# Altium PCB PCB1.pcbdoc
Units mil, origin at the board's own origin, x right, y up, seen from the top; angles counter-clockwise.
Board outline 3289.42 x 4778.44 mil, 2 copper layers (Top Layer, Bottom Layer); 55 components, 54 nets, 200 pads, 63 vias.
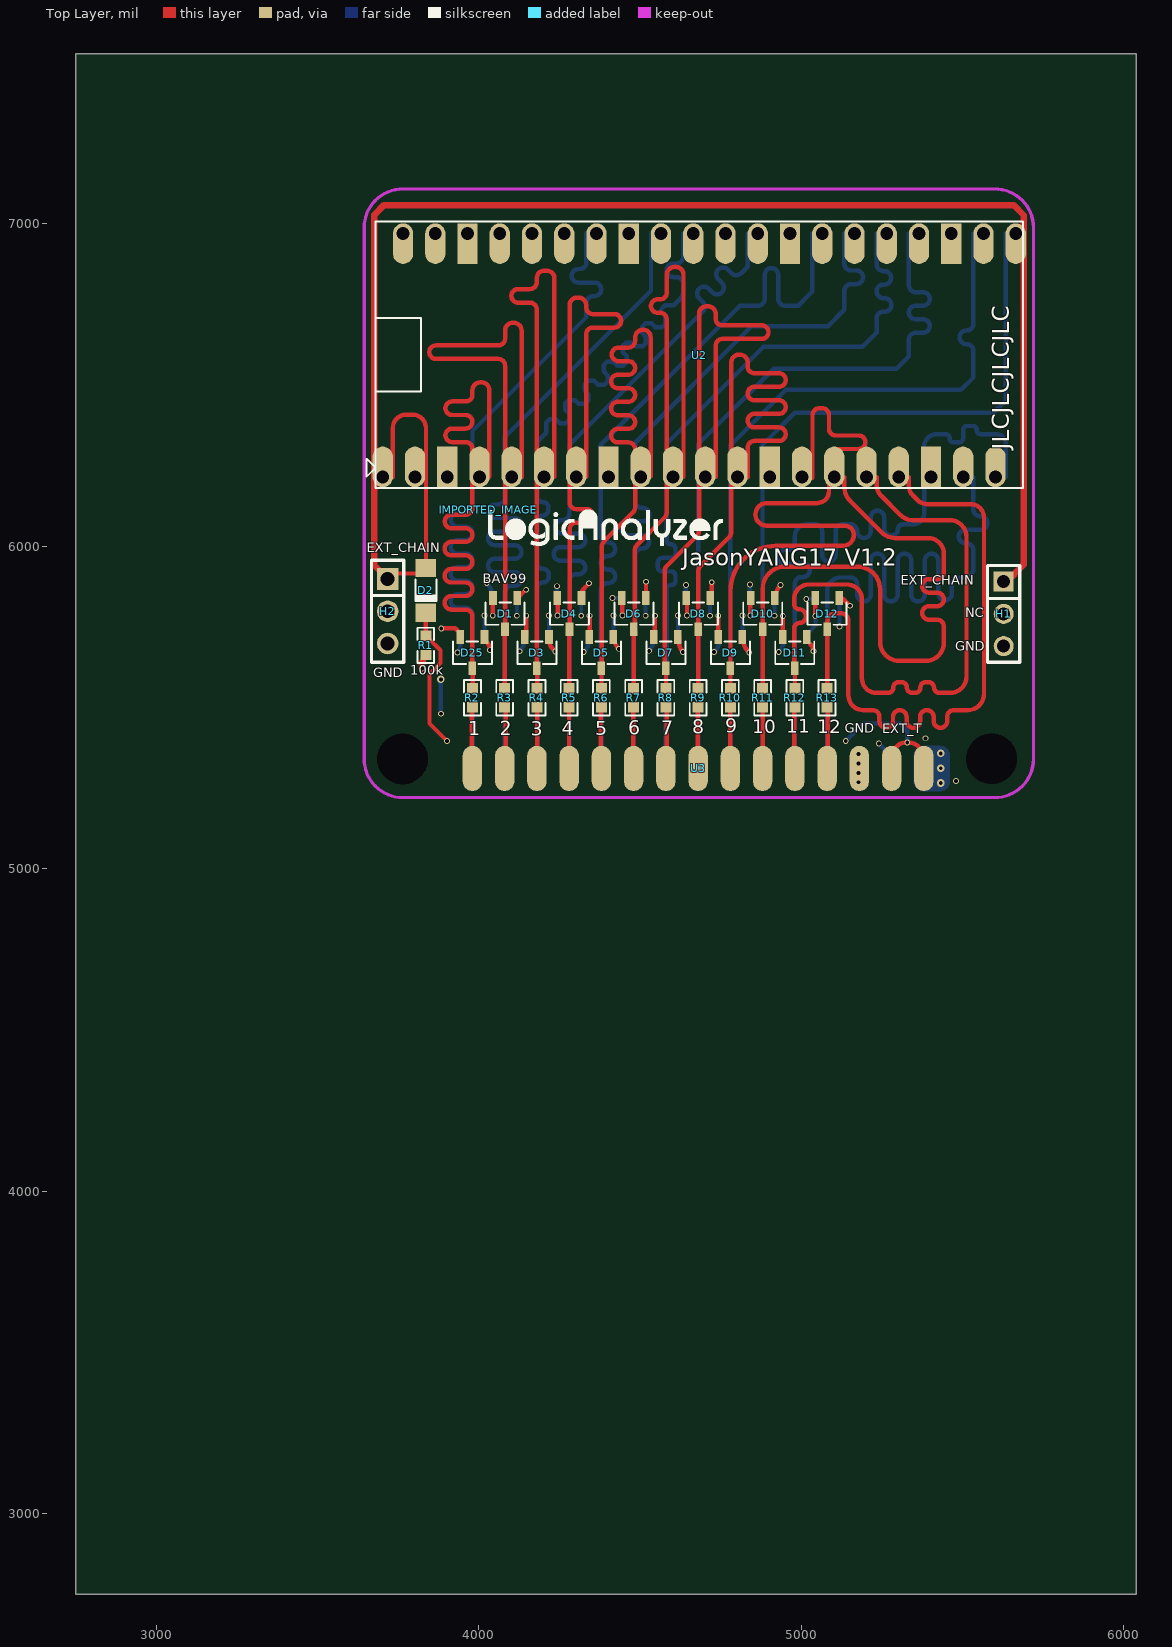
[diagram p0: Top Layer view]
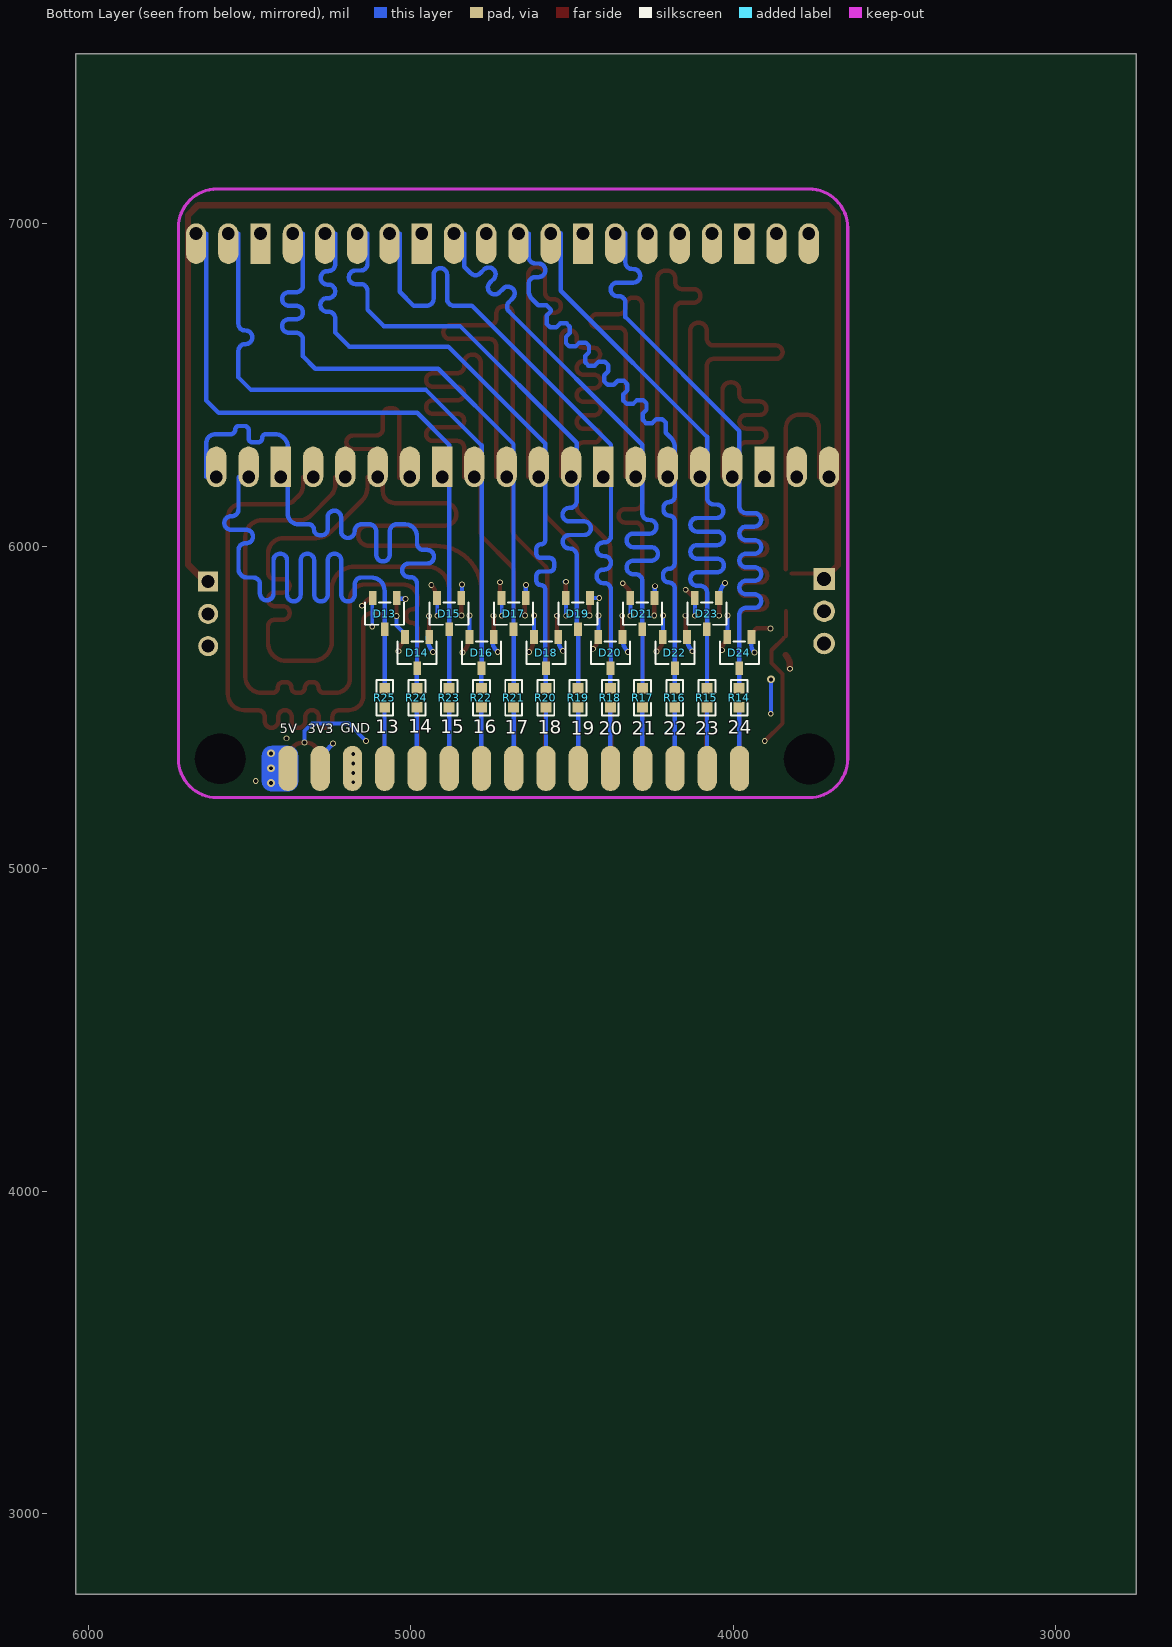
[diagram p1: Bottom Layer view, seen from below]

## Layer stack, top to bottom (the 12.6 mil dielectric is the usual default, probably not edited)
Top Layer: signal copper (thickness not stored)
Dielectric: dielectric 12.6, FR-4, Dk 4.8
Bottom Layer: signal copper (thickness not stored)

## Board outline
6039.42,2750 2750,2750 2750,7528.44 6039.42,7528.44
cut-out: 3842.69,5340.86 ccw(c3764.19,5340.86) 3685.69,5340.86 ccw(c3764.19,5340.86)
cut-out: 5669.28,5341.59 ccw(c5590.78,5341.59) 5512.28,5341.59 ccw(c5590.78,5341.59)

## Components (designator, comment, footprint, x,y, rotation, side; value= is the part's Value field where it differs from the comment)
D1 "BAV99,215" SOT-23-3_L2.9-W1.6-P1.90-LS2.8-BR 4081.8,5791.53 r90 top
D2 "FDLL4148" SOD-80_L3.5-W1.5-RD 3836.2,5863.79 r90 top
D3 "BAV99,215" SOT-23-3_L2.9-W1.6-P1.90-LS2.8-BR 4180.63,5670.41 r90 top
D4 "BAV99,215" SOT-23-3_L2.9-W1.6-P1.90-LS2.8-BR 4281.59,5791.53 r90 top
D5 "BAV99,215" SOT-23-3_L2.9-W1.6-P1.90-LS2.8-BR 4380.57,5670.41 r90 top
D6 "BAV99,215" SOT-23-3_L2.9-W1.6-P1.90-LS2.8-BR 4481.39,5791.53 r90 top
D7 "BAV99,215" SOT-23-3_L2.9-W1.6-P1.90-LS2.8-BR 4580.5,5670.41 r90 top
D8 "BAV99,215" SOT-23-3_L2.9-W1.6-P1.90-LS2.8-BR 4681.19,5791.53 r90 top
D9 "BAV99,215" SOT-23-3_L2.9-W1.6-P1.90-LS2.8-BR 4780.44,5670.41 r90 top
D10 "BAV99,215" SOT-23-3_L2.9-W1.6-P1.90-LS2.8-BR 4880.98,5791.53 r90 top
D11 "BAV99,215" SOT-23-3_L2.9-W1.6-P1.90-LS2.8-BR 4980.37,5670.41 r90 top
D12 "BAV99,215" SOT-23-3_L2.9-W1.6-P1.90-LS2.8-BR 5080.78,5791.53 r90 top
D13 "BAV99,215" SOT-23-3_L2.9-W1.6-P1.90-LS2.8-BR 5080.78,5791.53 r90 bottom
D14 "BAV99,215" SOT-23-3_L2.9-W1.6-P1.90-LS2.8-BR 4980.37,5670.41 r90 bottom
D15 "BAV99,215" SOT-23-3_L2.9-W1.6-P1.90-LS2.8-BR 4880.98,5791.53 r90 bottom
D16 "BAV99,215" SOT-23-3_L2.9-W1.6-P1.90-LS2.8-BR 4780.44,5670.41 r90 bottom
D17 "BAV99,215" SOT-23-3_L2.9-W1.6-P1.90-LS2.8-BR 4681.19,5791.53 r90 bottom
D18 "BAV99,215" SOT-23-3_L2.9-W1.6-P1.90-LS2.8-BR 4580.5,5670.41 r90 bottom
D19 "BAV99,215" SOT-23-3_L2.9-W1.6-P1.90-LS2.8-BR 4481.39,5791.53 r90 bottom
D20 "BAV99,215" SOT-23-3_L2.9-W1.6-P1.90-LS2.8-BR 4380.57,5670.41 r90 bottom
D21 "BAV99,215" SOT-23-3_L2.9-W1.6-P1.90-LS2.8-BR 4281.59,5791.53 r90 bottom
D22 "BAV99,215" SOT-23-3_L2.9-W1.6-P1.90-LS2.8-BR 4180.63,5670.41 r90 bottom
D23 "BAV99,215" SOT-23-3_L2.9-W1.6-P1.90-LS2.8-BR 4081.8,5791.53 r90 bottom
D24 "BAV99,215" SOT-23-3_L2.9-W1.6-P1.90-LS2.8-BR 3980.7,5670.41 r90 bottom
D25 "BAV99,215" SOT-23-3_L2.9-W1.6-P1.90-LS2.8-BR 3980.7,5670.41 r90 top
H1 "HDR-F_2.54_1x3P" HDR-TH_3P-P2.54-V-F 5628.17,5790.73 r270 top
H2 "HDR-M_2.54_1x3P" HDR-TH_3P-P2.54-V-M 3717.94,5799 r270 top
IMPORTED_IMAGE "IMPORTED_IMAGE" IMPORTED_IMAGE 4030.01,6114.17 r0 top
R1 "0603WAF1003T5E" R0603 3836.2,5693.26 r90 top
R2 "RC0603FR-07220RL" R0603 3980.7,5530.62 r270 top
R3 "RC0603FR-07220RL" R0603 4080.69,5530.62 r270 top
R4 "RC0603FR-07220RL" R0603 4180.68,5530.62 r270 top
R5 "RC0603FR-07220RL" R0603 4280.67,5530.62 r270 top
R6 "RC0603FR-07220RL" R0603 4380.66,5530.62 r270 top
R7 "RC0603FR-07220RL" R0603 4480.65,5530.62 r270 top
R8 "RC0603FR-07220RL" R0603 4580.64,5530.62 r270 top
R9 "RC0603FR-07220RL" R0603 4680.62,5530.62 r270 top
R10 "RC0603FR-07220RL" R0603 4780.61,5530.62 r270 top
R11 "RC0603FR-07220RL" R0603 4880.6,5530.62 r270 top
R12 "RC0603FR-07220RL" R0603 4980.59,5530.62 r270 top
R13 "RC0603FR-07220RL" R0603 5080.58,5530.62 r270 top
R14 "RC0603FR-07220RL" R0603 3981.38,5530.62 r90 bottom
R15 "RC0603FR-07220RL" R0603 4081.31,5530.62 r90 bottom
R16 "RC0603FR-07220RL" R0603 4181.24,5530.62 r90 bottom
R17 "RC0603FR-07220RL" R0603 4281.17,5530.62 r90 bottom
R18 "RC0603FR-07220RL" R0603 4381.09,5530.62 r90 bottom
R19 "RC0603FR-07220RL" R0603 4481.02,5530.62 r90 bottom
R20 "RC0603FR-07220RL" R0603 4580.95,5530.62 r90 bottom
R21 "RC0603FR-07220RL" R0603 4680.88,5530.62 r90 bottom
R22 "RC0603FR-07220RL" R0603 4780.8,5530.62 r90 bottom
R23 "RC0603FR-07220RL" R0603 4880.73,5530.62 r90 bottom
R24 "RC0603FR-07220RL" R0603 4980.66,5530.62 r90 bottom
R25 "RC0603FR-07220RL" R0603 5080.58,5530.62 r90 bottom
U2 "树莓派pico" 树莓派pico多层 5684.16,6181.42 r90 top
U3 "双排针母座2.54 2*15P" HDR-TH_30P-P2.54-V-F-R2-C15-S2.54-A 4628.47,5298.24 r90 top

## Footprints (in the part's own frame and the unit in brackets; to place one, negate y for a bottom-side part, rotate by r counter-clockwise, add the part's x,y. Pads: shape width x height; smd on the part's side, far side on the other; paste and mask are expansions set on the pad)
HDR-TH_3P-P2.54-V-F [mil]
  rect 62x62 hole 40.16 mask+2: 1(-100,0)
  round 62 hole 40.16 mask+2: 2(0,0) 3(100,0)
  silkscreen extent -150,-50 150,50
HDR-TH_3P-P2.54-V-M [mm]
  rect 1.7x1.7 hole 1.1 mask+0.051: 1(-2.54,0)
  round 1.7 hole 1.1 mask+0.051: 2(0,0) 3(2.54,0)
  silkscreen extent -4.02,-1.27 4.02,1.27
HDR-TH_30P-P2.54-V-F-R2-C15-S2.54-A [mil]
  oval 140x60 smd mask+2: 1(13.26,647.77) 2(13.26,547.77) 3(13.26,447.77) 4(13.26,347.77) 5(13.26,247.77) 6(13.26,147.77) 7(13.26,47.77) 8(13.26,-52.23) 9(13.26,-152.23) 10(13.26,-252.23) 11(13.26,-352.23) 12(13.26,-452.23) 13(13.26,-552.23) 14(13.26,-652.23) 15(13.26,-752.23)
  oval 140x60 smd far side mask+2: 16(13.26,-752.23) 17(13.26,-652.23) 18(13.26,-552.23) 19(13.26,-452.23) 20(13.26,-352.23) 21(13.26,-252.23) 22(13.26,-152.23) 23(13.26,-52.23) 24(13.26,47.77) 25(13.26,147.77) 26(13.26,247.77) 27(13.26,347.77) 28(13.26,447.77) 29(13.26,547.77) 30(13.26,647.77)
IMPORTED_IMAGE [mil]
  silkscreen extent 0,-112 727,0
R0603 [mil]
  rect 31.75x34.02 smd paste-3937.01 mask+2: 1(-29.66,0) 2(29.66,0)
  silkscreen extent -55,-26 55,26
SOD-80_L3.5-W1.5-RD [mm]
  rect 1.44x1.62 smd mask+0.051: 1(-1.765,0) 2(1.765,0)
  silkscreen extent -0.84,-0.83 0.84,0.83
SOT-23-3_L2.9-W1.6-P1.90-LS2.8-BR [mm]
  rect 1.07x0.6 smd mask+0.051: 1(1.235,-0.95) 2(1.235,0.95) 3(-1.235,0)
  silkscreen extent -0.88,-1.54 0.88,1.54
树莓派pico多层 [mm]
  oval 3.2x1.6 hole 1 copper offset 0.8,0 paste+0 mask+0.102: 1(0.86,50.33) 2(0.86,47.79) 4(0.86,42.71) 5(0.86,40.17) 6(0.86,37.63) 7(0.86,35.09) 9(0.86,30.01) 10(0.86,27.47) 11(0.86,24.93) 12(0.86,22.39) 14(0.86,17.31) 15(0.86,14.77) 16(0.86,12.23) 17(0.86,9.69) 19(0.86,4.61) 20(0.86,2.07)
  rect 3.2x1.6 hole 1 copper offset 0.8,0 paste+0 mask+0.102: 3(0.86,45.25) 8(0.86,32.55) 13(0.86,19.85) 18(0.86,7.15)
  oval 3.2x1.6 hole 1 copper offset -0.8,0 paste+0 mask+0.102: 21(20.04,0.47) 22(20.04,3.01) 24(20.04,8.09) 25(20.04,10.63) 26(20.04,13.17) 27(20.04,15.71) 29(20.04,20.79) 30(20.04,23.33) 31(20.04,25.87) 32(20.04,28.41) 34(20.04,33.49) 35(20.04,36.03) 36(20.04,38.57) 37(20.04,41.11) 39(20.04,46.19) 40(20.04,48.73)
  rect 3.2x1.6 hole 1 copper offset -0.8,0 paste+0 mask+0.102: 23(20.04,5.55) 28(20.04,18.25) 33(20.04,30.95) 38(20.04,43.65)
  silkscreen extent 0,-0.1 21,51.6

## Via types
v1: diameter 18, hole 12, Top Layer to Bottom Layer, 54 vias
v2: diameter 18, hole 12.01, Top Layer to Bottom Layer, 5 vias
v3: diameter 24.02, hole 12.01, Top Layer to Bottom Layer, 3 vias
v4: diameter 24, hole 12, Top Layer to Bottom Layer, 1 vias

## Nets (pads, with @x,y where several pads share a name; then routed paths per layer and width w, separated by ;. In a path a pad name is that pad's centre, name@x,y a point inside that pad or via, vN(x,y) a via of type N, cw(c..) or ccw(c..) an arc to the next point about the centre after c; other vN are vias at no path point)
$1N6412: R2.2 U3.1 | length 188.7
  Top Layer w13.75: U3.1@3979.1,5310.98 R2.2@3979.1,5499.7
$1N6457: R3.2 U3.2 | length 179.5
  Top Layer w13.75: U3.2@4083.95,5316.22 R3.2@4083.95,5495.77
$1N6576: R4.2 U3.3 | length 157.4
  Top Layer w13.75: U3.3@4183.33,5346 4181.65,5347.68 4181.65,5500.27 R4.2@4183.33,5501.96
$1N6580: R5.2 U3.4 | length 180.9
  Top Layer w13.75: U3.4@4280.31,5315.86 R5.2@4280.31,5496.72
$1N6666: R6.2 U3.5 | length 159.9
  Top Layer w13.75: U3.5@4378.6,5337.48 R6.2@4378.6,5497.37
$1N6670: R7.2 U3.6 | length 179.7
  Top Layer w13.75: U3.6@4480.11,5318.1 R7.2@4480.11,5497.79
$1N6756: R8.2 U3.7 | length 168.4
  Top Layer w13.75: U3.7@4582.84,5329.02 R8.2@4582.84,5497.43
$1N6760: R9.2 U3.8 | length 151.4
  Top Layer w13.75: U3.8@4679.17,5345.4 R9.2@4679.17,5496.77
$1N6846: R10.2 U3.9 | length 159.2
  Top Layer w13.75: U3.9@4776.15,5342.12 4780.74,5346.71 R10.2@4780.74,5499.39
$1N6850: R11.2 U3.10 | length 180.4
  Top Layer w13.75: R11.2@4880.56,5500.48 4880.56,5325.38 U3.10@4884.27,5321.66
$1N6936: R12.2 U3.11 | length 170.1
  Top Layer w13.75: U3.11@4978.7,5327.2 R12.2@4978.7,5497.28
$1N6940: R13.2 U3.12 | length 161.9
  Top Layer w13.75: U3.12@5082.16,5335.53 R13.2@5082.16,5497.46
$1N7395: R25.1 U3.19 | length 189.5
  Bottom Layer w13.75: U3.19@5081.32,5311.99 R25.1@5081.32,5501.48
$1N7399: R24.1 U3.20 | length 190.8
  Bottom Layer w13.75: U3.20@4980.99,5312.32 R24.1@4980.99,5503.13
$1N7403: R23.1 U3.21 | length 189
  Bottom Layer w13.75: U3.21@4880.4,5309.73 R23.1@4880.4,5498.73
$1N7407: R22.1 U3.22 | length 185
  Bottom Layer w13.75: U3.22@4780.72,5309.73 R22.1@4780.72,5494.78
$1N7411: R21.1 U3.23 | length 186.5
  Bottom Layer w13.75: U3.23@4680.67,5310.6 R21.1@4680.67,5497.12
$1N7415: R20.1 U3.24 | length 188.5
  Bottom Layer w13.75: U3.24@4580.5,5311.58 R20.1@4580.5,5500.08
$1N7419: R19.1 U3.25 | length 191
  Bottom Layer w13.75: U3.25@4480.33,5311.09 R19.1@4480.33,5502.06
$1N7423: R18.1 U3.26 | length 189
  Bottom Layer w13.75: U3.26@4381.25,5310.88 R18.1@4381.25,5499.88
$1N7427: R17.1 U3.27 | length 185
  Bottom Layer w13.75: U3.27@4281.57,5310.88 R17.1@4281.57,5495.93
$1N7431: R16.1 U3.28 | length 186.5
  Bottom Layer w13.75: U3.28@4181.52,5311.75 R16.1@4181.52,5498.27
$1N7435: R15.1 U3.29 | length 188.5
  Bottom Layer w13.75: U3.29@4081.35,5312.73 R15.1@4081.35,5501.24
$1N7439: R14.1 U3.30 | length 191
  Bottom Layer w13.75: U3.30@3981.18,5312.24 R14.1@3981.18,5503.21
+3.3V: D1.2 D3.2 D4.2 D5.2 D6.2 D7.2 D8.2 D9.2 D10.2 D11.2 D12.2 D13.2 D14.2 D15.2 D16.2 D17.2 D18.2 D19.2 D20.2 D21.2 D22.2 D23.2 D24.2 D25.2 U2.36 U3.17 | length 6001
  Top Layer w13.75: v1(3883.9,5745.91) 3927.47,5745.91 3941.99,5731.39 D25.2@3941.99,5717.47 ; v1(4043.93,5785.29) D1.2@4043.93,5841.22 ; D3.2@4142.89,5717.97 4147.53,5722.61 v1(4147.53,5785.32) ; v1(4244.76,5785.5) D4.2@4244.76,5841.38 ; D5.2@4344.12,5721.22 v1(4344.12,5785.29) ; v1(4445.85,5785.55) D6.2@4445.85,5830.77 ; D7.2@4543.21,5725.08 4546.46,5728.32 v1(4546.46,5784.88) ; v1(4646.08,5785.58) D8.2@4646.08,5842.73 ; D9.2@4743.21,5721.18 v1(4743.21,5785.26) ; v1(4842.79,5785.71) D10.2@4842.79,5837.73 ; D11.2@4943.32,5715.8 v1(4943.32,5783.98) ; v1(5044.17,5784.25) D12.2@5044.17,5837.67
  Inner2 w13.75: v2(3883.64,5481.2) 3921.02,5443.83 5185.96,5443.83 v2(5241.03,5388.76)
  Inner2 w20: v4(3882.74,5587.75) 3883.22,5588.23 3883.22,5733.07 ; 4134.17,6970.41 4134.17,6844.62 3883.22,6593.67 3883.22,5837.2 ; 3883.22,5733.07 cw(c3935.29,5733.07) 3884.78,5745.7 cw(c3935.29,5733.07) 3935.29,5785.14 cw(c3935.29,5837.2) 3883.22,5837.2 ; 3883.22,5733.07 3883.22,5837.2
  Inner2 w30: 3897.08,5785.14 3935.29,5785.14 v1(4118.38,5785.1) v1(4318.22,5785.12) v1(4518.02,5785.12) 4717.85,5785.14 4917.66,5785.14 5086.24,5785.14 v1(5119.3,5752.08)
  Bottom Layer w12: D24.2@4018.08,5713.56 v1(4018.08,5785.46) ; v1(4118.38,5785.1) 4118.38,5839.44 D23.2@4119.05,5840.11 ; D22.2@4218.09,5713.51 v1(4218.09,5785.41) ; v1(4318.22,5785.12) 4318.22,5839.46 D21.2@4318.89,5840.13 ; D20.2@4417.92,5713.59 v1(4417.92,5785.49) ; v1(4518.02,5785.12) 4518.02,5839.46 D19.2@4518.69,5840.13 ; D18.2@4617.88,5713.61 v1(4617.88,5785.51) ; v1(4717.85,5785.16) 4717.85,5839.5 D17.2@4718.53,5840.18 ; D16.2@4817.8,5713.63 v1(4817.8,5785.54) ; v1(4917.66,5785.05) 4917.66,5839.39 D15.2@4918.33,5840.06 ; D14.2@5017.77,5713.62 5017.77,5728.29 5044.17,5754.68 v1(5044.17,5784.25) ; D13.2 5119.3,5839.04 v1(5119.3,5752.08)
  Bottom Layer w13.75: v4(3882.74,5587.75) 3882.74,5482.11 v2(3883.64,5481.2) ; v1@3883.9,5744.89 v1(3883.9,5745.91) ; v1(4043.93,5785.29) v1@4046.55,5785.29 ; v1(4147.53,5785.32) v1@4148.32,5785.32 ; v1(4344.12,5785.29) v1@4345.14,5785.29 ; v1@4445.39,5785.55 v1(4445.85,5785.55) ; v1(4546.46,5784.88) v1@4548.51,5784.88 ; v1(4646.08,5785.58) v1@4648.64,5785.58 ; v1(4743.21,5785.26) v1@4743.47,5785.26 ; v1(4943.32,5783.98) v1@4945.88,5783.98 ; v2(5241.03,5388.76) cw(c5073.26,5220.99) U3.17@5281.73,5334.27
+5V: U2.40 U3.16 | length 3261.8
  Inner2 w20: 3729.38,6941.37 3782.89,6887.86 3782.89,5571.82 3826.91,5527.8 3921.47,5527.8 3953.21,5496.07 5362.34,5496.07 5433.07,5425.34 v3(5433.07,5358.29)
  Inner2 w24: v3(5433.07,5266.11) v3(5433.07,5312.2) v3(5433.07,5358.29)
CHAN_0: D25.3 R2.1 U2.4 | length 2090.5
  Top Layer w13.75: D25.3@3980.78,5612.44 3980.78,5783.23 ccw(c3959.78,5783.23) 3959.78,5804.23 3915.5,5804.23 cw(c3915.5,5825.23) 3915.5,5846.23 3959.78,5846.23 ccw(c3959.78,5867.23) 3959.78,5888.23 3915.5,5888.23 cw(c3915.5,5909.23) 3915.5,5930.23 3959.78,5930.23 ccw(c3959.78,5951.23) 3959.78,5972.23 3915.5,5972.23 cw(c3915.5,5993.23) 3915.5,6014.23 3959.78,6014.23 ccw(c3959.78,6035.23) 3959.78,6056.23 3916.16,6056.23 cw(c3916.16,6077.23) 3916.16,6098.23 3959.78,6098.23 ccw(c3959.78,6119.23) 3980.78,6119.23 3980.78,6302.57 ccw(c3959.78,6302.57) 3959.78,6323.57 3917.99,6323.57 cw(c3917.99,6344.57) 3917.99,6365.57 3959.78,6365.57 ccw(c3959.78,6386.57) 3959.78,6407.57 3917.99,6407.57 cw(c3917.99,6428.57) 3917.99,6449.57 3959.78,6449.57 ccw(c3959.78,6470.57) 3980.78,6470.57 3980.78,6484.63 cw(c4004.78,6484.63) 4004.78,6508.63 4009.25,6508.63 cw(c4009.25,6484.63) 4033.25,6484.63 U2.4@4033.25,6215.77 ; R2.1@3981.12,5560.25 D25.3@3981.12,5622.12
CHAN_1: D1.3 R3.1 U2.5 | length 2090.7
  Top Layer w13.75: R3.1@4080.95,5560.28 D1.3@4080.95,5743.3 ; D1.3@4082.01,5728.97 4082.01,6560.48 ccw(c4061.01,6560.48) 4061.01,6581.48 3867.93,6581.48 cw(c3867.93,6602.48) 3867.93,6623.48 4061.01,6623.48 ccw(c4061.01,6644.48) 4082.01,6644.48 4082.01,6669.67 cw(c4106.01,6669.67) 4106.01,6693.67 4109.03,6693.67 cw(c4109.03,6669.67) 4133.03,6669.67 U2.5@4133.03,6215.21
CHAN_2: D3.3 R4.1 U2.6 | length 2090.5
  Top Layer w13.75: D3.3@4179.9,5621.26 4179.9,6735.04 ccw(c4158.9,6735.04) 4158.9,6756.04 4122.53,6756.04 cw(c4122.53,6777.04) 4122.53,6798.04 4158.9,6798.04 ccw(c4158.9,6819.04) 4179.9,6819.04 4179.9,6831.3 cw(c4203.9,6831.3) 4203.9,6855.3 4211.07,6855.3 cw(c4211.07,6831.3) 4235.07,6831.3 4235.07,6215.95 ; R4.1@4181.1,5560.25 D3.3@4181.1,5622.12
CHAN_3: D4.3 R5.1 U2.7 | length 2091.5
  Top Layer w13.75: D4.3@4280.2,5742.26 D4.3@4280.93,5742.99 ; R5.1@4280.93,5560.28 D4.3@4280.93,5742.99 ; U2.7@4333.44,6215.48 4333.44,6657.61 cw(c4354.44,6657.61) 4354.44,6678.61 4420.83,6678.61 ccw(c4420.83,6699.61) 4420.83,6720.61 4354.44,6720.61 cw(c4354.44,6741.61) 4333.44,6741.61 4333.44,6747.76 ccw(c4309.44,6747.76) 4309.44,6771.76 4305.91,6771.76 ccw(c4305.91,6747.76) 4281.91,6747.76 4281.91,6136.9 ccw(c4302.91,6136.9) 4302.91,6115.9 4334.23,6115.9 cw(c4334.23,6094.9) 4334.23,6073.9 4302.91,6073.9 ccw(c4302.91,6052.9) 4281.91,6052.9 4281.91,5743.96 D4.3@4280.93,5742.99
CHAN_4: D5.3 R6.1 U2.9 | length 2090.6
  Top Layer w13.75: R6.1@4381.08,5560.25 D5.3@4381.08,5622.12 ; D5.3@4381.94,5612.79 4381.94,5998.71 cw(c4405.94,5998.71) 4388.97,6015.68 4478.2,6104.91 ccw(c4461.23,6121.88) 4485.23,6121.88 4485.23,6301.59 ccw(c4464.23,6301.59) 4464.23,6322.59 4431.93,6322.59 cw(c4431.93,6343.59) 4431.93,6364.59 4464.23,6364.59 ccw(c4464.23,6385.59) 4464.23,6406.59 4431.93,6406.59 cw(c4431.93,6427.59) 4431.93,6448.59 4464.23,6448.59 ccw(c4464.23,6469.59) 4464.23,6490.59 4431.93,6490.59 cw(c4431.93,6511.59) 4431.93,6532.59 4464.23,6532.59 ccw(c4464.23,6553.59) 4464.23,6574.59 4433.79,6574.59 cw(c4433.79,6595.59) 4433.79,6616.59 4464.23,6616.59 ccw(c4464.23,6637.59) 4485.23,6637.59 4485.23,6647.4 cw(c4510.01,6647.4) 4510.01,6672.17 cw(c4510.01,6649.06) 4533.13,6649.06 U2.9@4533.13,6217.42
CHAN_5: D6.3 R7.1 U2.10 | length 2090.7
  Top Layer w13.75: R7.1@4480.91,5560.28 D6.3@4480.91,5743.3 ; D6.3@4483.7,5742.99 4483.7,5986.99 cw(c4507.7,5986.99) 4490.73,6003.96 4576.55,6089.78 ccw(c4559.58,6106.75) 4583.58,6106.75 4583.58,6703.38 ccw(c4562.58,6703.38) 4562.58,6724.38 4555.3,6724.38 cw(c4555.3,6745.38) 4555.3,6766.38 4562.58,6766.38 ccw(c4562.58,6787.38) 4583.58,6787.38 4583.58,6842.69 cw(c4607.58,6842.69) 4607.58,6866.69 4611.29,6866.69 cw(c4611.29,6842.69) 4635.29,6842.69 4635.29,6215.63
CHAN_6: D7.3 R8.1 U2.11 | length 2090.6
  Top Layer w13.75: D7.3@4576.52,5610.47 4576.52,5922.42 cw(c4600.52,5922.42) 4583.55,5939.39 4676.51,6032.35 ccw(c4659.54,6049.32) 4683.54,6049.32 4683.54,6721.1 cw(c4707.54,6721.1) 4707.54,6745.1 4710.97,6745.1 cw(c4710.97,6721.1) 4734.97,6721.1 4734.97,6706.56 ccw(c4755.97,6706.56) 4755.97,6685.56 4878,6685.56 cw(c4878,6664.56) 4878,6643.56 4755.97,6643.56 ccw(c4755.97,6622.56) 4734.97,6622.56 4734.97,6216.09 ; R8.1@4581.06,5560.25 D7.3@4581.06,5622.12
CHAN_7: D8.3 R9.1 U2.12 | length 2090.3
  Top Layer w13.75: R9.1@4680.89,5560.28 D8.3@4680.89,5743.3 ; D8.3@4681.1,5738.06 4681.1,5922.38 cw(c4706.1,5922.38) 4688.42,5940.05 4775.92,6027.56 ccw(c4758.25,6045.23) 4783.24,6045.23 4783.24,6570.09 cw(c4808.24,6570.09) 4808.24,6595.09 4809.28,6595.09 cw(c4809.28,6570.09) 4834.28,6570.09 4834.29,6558.1 ccw(c4855.29,6558.1) 4855.29,6537.1 4931.29,6537.11 cw(c4931.29,6516.11) 4931.29,6495.11 4855.29,6495.1 ccw(c4855.29,6474.1) 4855.29,6453.1 4931.29,6453.11 cw(c4931.29,6432.11) 4931.29,6411.11 4855.29,6411.1 ccw(c4855.29,6390.1) 4855.29,6369.1 4931.29,6369.11 cw(c4931.29,6348.11) 4931.29,6327.11 4855.29,6327.1 ccw(c4855.29,6306.1) 4834.29,6306.1 4834.29,6214.42
CHAN_8: D9.3 R10.1 U2.14 | length 2092.9
  Top Layer w13.75: R10.1@4781.04,5560.25 D9.3@4781.04,5621.49 ; D9.3@4783.13,5619.4 D9.3@4781.04,5621.49 ; 5035.36,6212.69 5035.36,6406.56 cw(c5057.61,6406.56) 5057.61,6428.81 5065.09,6428.81 cw(c5065.09,6407.46) 5086.44,6407.46 5086.44,6365.08 ccw(c5107.44,6365.08) 5107.44,6344.08 5178.56,6344.08 cw(c5178.56,6323.08) 5178.56,6302.08 5107.44,6302.08 ccw(c5107.44,6281.08) 5086.44,6281.08 5086.44,6171.23 cw(c5049.76,6171.23) 5049.76,6134.55 4893.9,6134.55 ccw(c4893.9,6099.02) 4858.37,6099.02 ccw(c4892.74,6099.02) 4892.74,6064.65 5134.55,6064.65 cw(c5134.55,6035.78) 5163.42,6035.78 cw(c5129.37,6035.78) 5129.37,6001.73 4920.93,6001.73 ccw(c4920.93,5861.84) 4781.04,5861.84 D9.3@4781.04,5621.49
CHAN_9: D10.3 R11.1 U2.15 | length 2090.7
  Top Layer w13.75: R11.1@4880.87,5560.28 D10.3@4880.87,5743.3 ; D10.3@4881.14,5744.95 4881.14,5868.94 cw(c4949.36,5868.94) 4949.36,5937.15 5174.76,5937.15 cw(c5174.76,5867) 5244.91,5867 5244.91,5704.32 ccw(c5304.21,5704.32) 5304.21,5645.03 5386.37,5645.03 ccw(c5386.37,5701.28) 5442.62,5701.28 5442.62,5751.75 ccw(c5421.62,5751.75) 5421.62,5772.75 5396.46,5772.75 cw(c5396.46,5793.75) 5396.46,5814.75 5421.62,5814.75 ccw(c5421.62,5835.75) 5421.62,5856.75 5396.69,5856.75 cw(c5396.69,5877.75) 5396.69,5898.75 5421.62,5898.75 ccw(c5421.62,5919.75) 5442.62,5919.75 5442.62,5977.59 ccw(c5394.39,5977.59) 5394.39,6025.82 5292.35,6025.82 cw(c5292.35,6085.82) 5249.93,6043.39 5151.74,6141.58 cw(c5194.17,6184) 5134.17,6184 5134.17,6215.29
CHAN_10: D11.3 R12.1 U2.16 | length 2090.3
  Top Layer w13.75: D11.3@4978.11,5629.48 4978.11,5744.86 cw(c4995.97,5744.86) 4995.97,5762.72 ccw(c4995.97,5780.58) 5013.83,5780.58 5013.83,5786.86 ccw(c4995.97,5786.86) 4995.97,5804.72 cw(c4995.97,5822.58) 4978.11,5822.58 4978.11,5836.45 cw(c5023.62,5836.45) 5023.62,5881.96 5142.79,5881.96 cw(c5142.79,5836.07) 5188.68,5836.07 5188.68,5590.33 ccw(c5233.09,5590.33) 5233.09,5545.92 5269.53,5545.92 ccw(c5269.53,5562.43) 5286.04,5562.43 cw(c5302.56,5562.43) 5302.56,5578.95 5311.53,5578.95 cw(c5311.53,5562.43) 5328.04,5562.43 ccw(c5344.56,5562.43) 5344.56,5545.92 5353.53,5545.92 ccw(c5353.53,5562.43) 5370.04,5562.43 cw(c5386.56,5562.43) 5386.56,5578.95 5395.53,5578.95 cw(c5395.53,5562.43) 5412.04,5562.43 ccw(c5428.56,5562.43) 5428.56,5545.92 5462.55,5545.92 ccw(c5462.55,5596.25) 5512.88,5596.25 5512.88,6029.5 ccw(c5460.78,6029.5) 5460.78,6081.6 5344.66,6081.6 cw(c5344.66,6131.6) 5309.3,6096.24 5248.81,6156.73 cw(c5284.17,6192.08) 5234.17,6192.08 5234.17,6215.29 ; R12.1@4981.02,5560.25 D11.3@4981.02,5622.12
CHAN_11: D12.3 R13.1 U2.17 | length 2088
  Top Layer w13.75: R13.1@5080.85,5560.28 D12.3@5080.85,5742.91 ; D12.3@5081.68,5742.16 5081.68,5767.33 cw(c5107.34,5767.33) 5107.34,5792.99 5122.64,5792.99 cw(c5122.64,5768.81) 5146.82,5768.81 5146.82,5537.93 ccw(c5192.52,5537.93) 5192.52,5492.23 5221.96,5492.23 cw(c5221.96,5471.23) 5242.96,5471.23 5242.96,5458.63 ccw(c5263.96,5458.63) 5284.96,5458.63 5284.96,5471.23 cw(c5305.96,5471.23) 5326.96,5471.23 5326.96,5458.63 ccw(c5347.96,5458.63) 5368.96,5458.63 5368.96,5471.23 cw(c5389.96,5471.23) 5410.96,5471.23 5410.96,5458.63 ccw(c5431.96,5458.63) 5452.96,5458.63 5452.96,5471.23 cw(c5473.96,5471.23) 5473.96,5492.23 5516.66,5492.23 ccw(c5516.66,5542.67) 5567.11,5542.67 5567.11,6089.73 ccw(c5525.4,6089.73) 5525.4,6131.44 5390.07,6131.44 cw(c5390.07,6171.44) 5361.79,6143.16 5345.89,6159.06 cw(c5374.17,6187.34) 5334.17,6187.34 5334.17,6215.29
CHAN_12: D13.3 R25.2 U2.19 | length 2091.1
  Bottom Layer w13.75: R25.2@5080.6,5560.57 D13.3@5080.6,5744.1 ; D13.3@5081.04,5743.01 5081.04,5862.61 cw(c5122.14,5862.61) 5122.14,5903.71 5152.63,5903.71 cw(c5152.63,5882.71) 5173.63,5882.71 5173.63,5850.53 ccw(c5194.63,5850.53) 5215.63,5850.53 5215.63,5956.89 cw(c5236.63,5956.89) 5257.63,5956.89 5257.63,5850.53 ccw(c5278.63,5850.53) 5299.63,5850.53 5299.63,5956.89 cw(c5320.63,5956.89) 5341.63,5956.89 5341.63,5850.53 ccw(c5362.63,5850.53) 5383.63,5850.53 5383.63,5956.89 cw(c5404.63,5956.89) 5425.63,5956.89 5425.63,5854.08 ccw(c5446.63,5854.08) 5467.63,5854.08 5467.63,5882.71 cw(c5488.63,5882.71) 5488.63,5903.71 5507.65,5903.71 ccw(c5507.65,5930.25) 5534.19,5930.25 5534.19,5988.7 ccw(c5513.19,5988.7) 5513.19,6009.7 5510,6009.7 cw(c5510,6030.7) 5510,6051.7 5557.09,6051.7 ccw(c5557.09,6072.7) 5557.09,6093.7 5555.19,6093.7 cw(c5555.19,6114.7) 5534.19,6114.7 5534.19,6215.17
CHAN_13: D14.3 R24.2 U2.20 | length 2090.2
  Bottom Layer w13.75: D14.3@4980.59,5622.04 4980.59,5884.07 cw(c5001.59,5884.07) 5001.59,5905.07 5005.78,5905.07 ccw(c5005.78,5926.07) 5005.78,5947.07 4948.69,5947.07 cw(c4948.69,5968.07) 4948.69,5989.07 4959.59,5989.07 ccw(c4959.59,6010.07) 4980.59,6010.07 4980.59,6031.65 cw(c5017.37,6031.65) 5017.37,6068.42 5044.06,6068.42 cw(c5044.06,6047.42) 5065.06,6047.42 5065.06,5974.62 ccw(c5086.06,5974.62) 5107.06,5974.62 5107.06,6047.42 cw(c5128.06,6047.42) 5128.06,6068.42 5153.02,6068.42 cw(c5153.02,6047.42) 5174.02,6047.42 5174.02,6047.07 ccw(c5195.02,6047.07) 5216.02,6047.07 5216.02,6089.78 cw(c5237.02,6089.78) 5258.02,6089.78 5258.02,6051.85 ccw(c5274.59,6051.85) 5274.59,6035.28 5283.44,6035.28 ccw(c5283.44,6051.85) 5300.02,6051.85 cw(c5316.59,6051.85) 5316.59,6068.42 5347.7,6068.42 ccw(c5347.7,6102.25) 5381.53,6102.25 5381.53,6308.73 cw(c5421.06,6308.73) 5421.06,6348.26 5448,6348.26 cw(c5448,6335.61) 5460.65,6335.61 ccw(c5473.3,6335.61) 5473.3,6322.96 5490,6322.96 ccw(c5490,6335.61) 5502.65,6335.61 5502.65,6360.91 cw(c5515.3,6360.91) 5515.3,6373.56 5532,6373.56 cw(c5532,6360.91) 5544.65,6360.91 ccw(c5557.3,6360.91) 5557.3,6348.26 5605.11,6348.26 cw(c5605.11,6318.89) 5634.48,6318.89 5634.48,6215.33 ; R24.2@4980.93,5560.35 D14.3@4980.93,5621.76
CHAN_14: D15.3 R23.2 U2.21 | length 2091.2
  Bottom Layer w13.75: D15.3@4880.28,5735.8 4880.28,6314.49 4980.18,6414.39 5595.96,6414.39 5634.21,6452.64 U2.21@5634.21,6970.45 ; R23.2@4880.74,5560.57 D15.3@4880.74,5744.1
CHAN_15: D16.3 R22.2 U2.22 | length 2090.1
  Bottom Layer w13.75: D16.3@4780.4,5621.86 4780.4,6313.14 4952.58,6485.32 5495.41,6485.32 5534.29,6524.19 5534.29,6606.54 ccw(c5513.29,6606.54) 5513.29,6627.54 5512.31,6627.54 cw(c5512.31,6648.54) 5512.31,6669.54 5513.29,6669.54 ccw(c5513.29,6690.54) 5534.29,6690.54 U2.22@5534.29,6970.38 ; R22.2@4781.07,5560.35 D16.3@4781.07,5621.76
CHAN_16: D17.3 R21.2 U2.24 | length 2091.2
  Bottom Layer w13.75: R21.2@4680.89,5560.57 D17.3@4680.89,5744.1 ; D17.3@4681.32,5743.11 4681.32,6317.45 4914.92,6551.06 5295.89,6551.06 5334.25,6589.42 5334.25,6641.54 cw(c5355.25,6641.54) 5355.25,6662.54 5377.99,6662.54 ccw(c5377.99,6683.54) 5377.99,6704.54 5355.25,6704.54 cw(c5355.25,6725.54) 5355.25,6746.54 5377.97,6746.54 ccw(c5377.97,6767.54) 5377.97,6788.54 5355.25,6788.54 cw(c5355.25,6809.54) 5334.25,6809.54 U2.24@5334.25,6970.39
CHAN_17: D18.3 R20.2 U2.25 | length 2089.9
  Bottom Layer w13.75: R20.2@4581.22,5560.35 D18.3@4581.22,5621.76 ; D18.3@4583.02,5618.98 4583.02,5866.63 cw(c4596.73,5866.63) 4596.73,5880.34 ccw(c4596.73,5894.04) 4610.44,5894.04 4610.44,5908.63 ccw(c4596.73,5908.63) 4596.73,5922.34 4569.31,5922.34 cw(c4569.31,5936.04) 4555.6,5936.04 4555.6,5950.63 cw(c4569.31,5950.63) 4569.31,5964.34 4596.73,5964.34 ccw(c4596.73,5978.04) 4610.44,5978.04 4610.44,5992.63 ccw(c4596.73,5992.63) 4596.73,6006.34 cw(c4596.73,6020.04) 4583.02,6020.04 4583.02,6319.28 4883.13,6619.39 5190.08,6619.39 5234.21,6663.52 5234.21,6707.02 cw(c5255.21,6707.02) 5255.21,6728.02 5259.28,6728.02 ccw(c5259.28,6749.02) 5259.28,6770.02 5255.21,6770.02 cw(c5255.21,6791.02) 5255.21,6812.02 5258.19,6812.02 ccw(c5258.19,6833.02) 5258.19,6854.02 5255.21,6854.02 cw(c5255.21,6875.02) 5234.21,6875.02 U2.25@5234.21,6970.47
CHAN_18: D19.3 R19.2 U2.26 | length 2091.3
  Bottom Layer w13.75: R19.2@4481.03,5560.57 D19.3@4481.03,5744.1 ; D19.3@4485.38,5740.8 4485.38,5972.5 cw(c4506.38,5972.5) 4506.38,5993.5 4507.75,5993.5 ccw(c4507.75,6014.5) 4507.75,6035.5 4462.36,6035.5 cw(c4462.36,6056.5) 4462.36,6077.5 4508.39,6077.5 ccw(c4508.39,6098.5) 4508.39,6119.5 4506.38,6119.5 cw(c4506.38,6140.5) 4485.38,6140.5 4485.38,6321.62 4847.15,6683.4 5083.88,6683.4 5134.17,6733.68 5134.17,6792.6 cw(c5155.17,6792.6) 5155.17,6813.6 5171.19,6813.6 ccw(c5171.19,6834.6) 5171.19,6855.6 5155.17,6855.6 cw(c5155.17,6876.6) 5134.17,6876.6 5134.17,6970.41
CHAN_19: D20.3 R18.2 U2.27 | length 2090.1
  Bottom Layer w13.75: D20.3@4378.92,5622.46 4378.92,5865.33 cw(c4399.92,5865.33) 4399.92,5886.33 4402.59,5886.33 ccw(c4402.59,5907.33) 4402.59,5928.33 4399.92,5928.33 cw(c4399.92,5949.33) 4399.92,5970.33 4402.35,5970.33 ccw(c4402.35,5991.33) 4402.35,6012.33 4399.92,6012.33 cw(c4399.92,6033.33) 4378.92,6033.33 4378.92,6315.22 4810.23,6746.54 4866.17,6746.54 ccw(c4866.17,6767.54) 4887.17,6767.54 4887.17,6842.2 cw(c4908.17,6842.2) 4929.17,6842.2 4929.17,6767.54 ccw(c4950.17,6767.54) 4950.17,6746.54 4991.15,6746.54 5034.11,6789.5 5034.11,6970.41 ; R18.2@4381.36,5560.35 D20.3@4381.36,5621.76
CHAN_20: D21.3 R17.2 U2.29 | length 2091.2
  Bottom Layer w13.75: R17.2@4281.18,5560.57 D21.3@4281.18,5744.1 ; D21.3@4281.86,5742.78 4281.86,5892.87 cw(c4302.86,5892.87) 4302.86,5913.87 4309.61,5913.87 ccw(c4309.61,5934.87) 4309.61,5955.87 4254.11,5955.87 cw(c4254.11,5976.87) 4254.11,5997.87 4309.61,5997.87 ccw(c4309.61,6018.87) 4309.61,6039.87 4258.9,6039.87 cw(c4258.9,6060.87) 4258.9,6081.87 4260.86,6081.87 ccw(c4260.86,6102.87) 4281.86,6102.87 4281.86,6315.24 4695.17,6728.55 ccw(c4680.32,6743.4) 4695.17,6758.25 4683.67,6769.75 cw(c4698.52,6784.6) 4713.37,6799.45 4724.87,6787.95 ccw(c4739.72,6802.8) 4754.57,6817.64 4743.07,6829.15 cw(c4757.92,6844) 4772.77,6858.85 4784.27,6847.34 ccw(c4799.12,6862.19) 4813.97,6847.34 4834.16,6867.54 4834.16,6970.4
CHAN_21: D22.3 R16.2 U2.31 | length 2089.7
  Bottom Layer w13.75: D22.3@4181.37,5629.85 4181.37,5870.29 cw(c4199.51,5870.29) 4199.51,5888.42 ccw(c4199.51,5906.56) 4217.64,5906.56 4217.64,5912.29 ccw(c4199.51,5912.29) 4199.51,5930.42 cw(c4199.51,5948.56) 4181.37,5948.56 4181.37,6078.28 cw(c4198.77,6078.28) 4198.77,6095.68 ccw(c4198.77,6113.07) 4216.16,6113.07 4216.16,6120.28 ccw(c4198.77,6120.28) 4198.77,6137.68 cw(c4198.77,6155.07) 4181.37,6155.07 4181.37,6307.11 cw(c4223.91,6307.11) 4193.83,6337.19 4209.55,6352.91 4209.55,6384.34 4219.81,6394.59 4239.25,6394.59 4251.24,6382.6 4270.68,6382.6 4280.94,6392.86 4280.94,6412.3 4268.95,6424.29 4268.95,6443.74 4279.2,6453.99 4298.65,6453.99 4310.63,6442 4330.08,6442 4340.33,6452.25 4340.33,6471.7 4328.35,6483.69 4328.35,6503.13 4338.6,6513.39 4358.04,6513.39 4370.03,6501.4 4389.48,6501.4 4399.73,6511.65 4399.73,6531.1 4387.74,6543.08 4387.74,6562.53 4398,6572.78 4417.44,6572.78 4429.43,6560.8 4448.87,6560.8 4459.13,6571.05 4459.13,6590.49 4447.14,6602.48 4447.14,6621.93 4457.39,6632.18 4476.84,6632.18 4488.83,6620.19 4508.27,6620.19 4518.52,6630.44 4518.52,6649.89 4506.54,6661.88 4506.54,6681.32 4516.79,6691.58 4536.24,6691.58 4548.22,6679.59 4567.67,6679.59 4577.92,6689.84 4577.92,6716.26 4565.46,6728.73 4565.46,6734.52 4579.05,6748.11 4604.76,6748.11 4623.5,6766.85 ccw(c4597.65,6792.7) 4634.2,6792.7 4634.2,6814.4 ccw(c4613.2,6814.4) 4613.2,6835.4 4603.74,6835.4 cw(c4603.74,6856.4) 4603.74,6877.4 4613.2,6877.4 ccw(c4613.2,6898.4) 4634.2,6898.4 U2.31@4634.2,6970.46 ; R16.2@4181.51,5560.35 D22.3@4181.51,5621.76
CHAN_22: D23.3 R15.2 U2.32 | length 2091.2
  Bottom Layer w13.75: D23.3@4080.93,5744.85 4080.93,5857.07 cw(c4101.93,5857.07) 4101.93,5878.07 4111.88,5878.07 ccw(c4111.88,5899.07) 4111.88,5920.07 4049.99,5920.07 cw(c4049.99,5941.07) 4049.99,5962.07 4111.88,5962.07 ccw(c4111.88,5983.07) 4111.88,6004.07 4049.99,6004.07 cw(c4049.99,6025.07) 4049.99,6046.07 4111.88,6046.07 ccw(c4111.88,6067.07) 4111.88,6088.07 4051.62,6088.07 cw(c4051.62,6109.07) 4051.62,6130.07 4059.93,6130.07 ccw(c4059.93,6151.07) 4080.93,6151.07 4080.93,6339.57 4534.43,6793.06 U2.32@4534.43,6970.8 ; R15.2@4081.32,5560.57 D23.3@4081.32,5744.1
CHAN_23: D24.3 R14.2 U2.34 | length 2090.1
  Bottom Layer w13.75: D24.3@3980.91,5613.78 3980.91,5788.44 ccw(c3959.91,5788.44) 3959.91,5809.44 3934.24,5809.44 cw(c3934.24,5830.44) 3934.24,5851.44 3959.91,5851.44 ccw(c3959.91,5872.44) 3959.91,5893.44 3934.24,5893.44 cw(c3934.24,5914.44) 3934.24,5935.44 3959.91,5935.44 ccw(c3959.91,5956.44) 3959.91,5977.44 3934.24,5977.44 cw(c3934.24,5998.44) 3934.24,6019.44 3959.91,6019.44 ccw(c3959.91,6040.44) 3959.91,6061.44 3934.58,6061.44 cw(c3934.58,6082.44) 3934.58,6103.44 3959.91,6103.44 ccw(c3959.91,6124.44) 3980.91,6124.44 3980.91,6357.82 4334.31,6711.22 4334.31,6755.29 cw(c4355.31,6755.29) 4355.31,6776.29 4359.1,6776.29 ccw(c4359.1,6797.29) 4359.1,6818.29 4309.52,6818.29 cw(c4309.52,6839.29) 4309.52,6860.29 4313.31,6860.29 ccw(c4313.31,6881.29) 4334.31,6881.29 U2.34@4334.31,6970.54 ; R14.2@3981.65,5560.35 D24.3@3981.65,5621.76
EXT_CHAIN: D2.2 H1.1 H2.1 U2.1 U2.2 | length 5175.3
  Top Layer w13.75: H2.1@3730.29,5916.12 D2.2@3818.78,5916.12 ; U2.1@3733.89,6215.02 3733.89,6367.67 cw(c3774.54,6367.67) 3774.54,6408.32 3795.28,6408.32 cw(c3795.28,6366.84) 3836.76,6366.84 3836.76,6224.15 ; D2.2@3836.76,5929.63 3836.76,6222.49
  Top Layer w20: H2.1@3718.66,5899.33 3675.96,5942.03 3675.96,7028.12 3706.52,7058.68 5659.49,7058.68 5690.73,7027.44 5690.73,5943.81 H1.1@5635.29,5888.37
EXT_T: D2.1 R1.2 U3.14 U3.15 | length 2077
  Top Layer w13: R1.2@3844.42,5715.04 3881.47,5677.98 3881.47,5638.16 3847.55,5604.24 3847.55,5451.46 3902.18,5396.83 v2(3902.18,5396.28)
  Top Layer w13.75: R1.2@3836.3,5722.97 D2.1@3836.3,5798.92 ; U3.14@5285.95,5352.47 cw(c5325.77,5352.47) 5325.77,5392.29 5332.96,5392.29 cw(c5332.96,5350.26) U3.15@5374.99,5350.26
  Inner2 w13: v2(3902.18,5396.28) 3902.92,5397.02 v2(5138.56,5397.02)
  Bottom Layer w13: v2(5138.56,5397.02) 5192.03,5450.48 5306.61,5450.48 5329.31,5427.78 v2(5329.31,5392.25)
GND: D1.1 D3.1 D4.1 D5.1 D6.1 D7.1 D8.1 D9.1 D10.1 D11.1 D12.1 D13.1 D14.1 D15.1 D16.1 D17.1 D18.1 D19.1 D20.1 D21.1 D22.1 D23.1 D24.1 D25.1 H1.3 H2.3 R1.1 U2.3 U2.8 U2.13 U2.18 U2.23 U2.28 U2.38 U3.13 U3.18 | length 1085.9
  Top Layer w13.75: D25.1@4016.05,5713.17 4024.07,5705.16 cw(c3997.17,5678.27) v1(4035.2,5678.27) ; v1@4024.87,5886.25 v1(4025.13,5886.25) ; D1.1@4121.53,5841.16 4143.81,5863.44 cw(c4148.19,5859.07) v1@4148.19,5865.26 ; D3.1@4217.5,5713.17 ccw(c4262.97,5713.17) 4230.82,5681.02 v1(4237.87,5673.96) ; D4.1@4318.04,5846.48 cw(c4353.31,5846.48) 4328.37,5871.42 v1(4342.65,5885.69) ; v1@4415.52,5839.32 v1(4415.52,5840.09) ; D5.1@4418.94,5720.47 ccw(c4472.75,5720.47) v1(4434.7,5682.42) ; D6.1@4518.97,5843.41 v1(4518.97,5890.31) ; D7.1@4621.54,5714.58 4621.54,5701.63 ccw(c4662.66,5701.63) v1(4633.58,5672.55) ; v1@4642.22,5880.12 v1(4642.73,5880.12) ; D8.1@4723.08,5848.01 v1(4723.08,5888.85) ; D9.1@4818.62,5718.49 ccw(c4883.59,5718.49) 4837.65,5672.55 v1(4839.12,5671.08) ; v1(4841.1,5881.92) v1@4842.9,5881.92 ; D10.1@4921.8,5839.72 4921.8,5845.31 cw(c4970.81,5845.31) v1(4936.16,5879.96) ; D11.1@5015.84,5710.35 5028.89,5697.3 cw(c5006.58,5674.99) v1(5038.13,5674.99) ; v1(5016.15,5837.32) v1@5016.15,5838.35 ; D12.1@5120.72,5839.63 cw(c5120.72,5822.3) 5132.97,5834.55 v1(5151.47,5816.05)
  Top Layer w20: v1(3824.01,5620.6) 3824.01,5630.79 cw(c3869.95,5630.79) R1.1@3837.46,5663.28
  Bottom Layer w13.75: v1(3934.4,5671.25) ccw(c3912.12,5693.52) 3943.63,5693.52 D24.1@3943.63,5720.46 ; v1(4025.13,5886.25) 4025.5,5885.88 cw(c3985.25,5845.63) D23.1@4042.17,5845.63 ; v1(4126.62,5675.09) ccw(c4085.78,5715.93) 4143.53,5715.93 D22.1@4143.53,5716.23 ; D21.1@4242.78,5837.78 v1(4242.78,5876.73) ; v1(4326.14,5672.79) 4326.97,5673.62 ccw(c4286.28,5714.3) D20.1@4343.82,5714.3 ; v1(4415.52,5840.09) D19.1@4442.69,5840.09 ; v1(4518.97,5890.31) v1@4521.79,5890.31 ; v1(4528.35,5676.25) ccw(c4494.94,5709.66) 4542.19,5709.66 D18.1@4542.19,5713.15 ; D17.1@4642.73,5841.94 v1(4642.73,5880.12) ; v1@4721.55,5888.85 v1(4723.08,5888.85) ; v1(4730.18,5672.4) 4732.53,5674.75 ccw(c4696.43,5710.84) D16.1@4747.48,5710.84 ; D15.1@4841.1,5835.53 v1(4841.1,5881.92) ; v1(4930.59,5672.53) ccw(c4891.92,5711.2) 4946.61,5711.2 D14.1@4946.61,5719.69 ; v1(5016.15,5837.32) D13.1@5045.36,5837.32
  other v1: 5178.18,5268.52 5480.55,5272.23 5178.18,5297.91 5178.18,5327.3 5178.18,5356.69 5385.37,5404.89 4147.42,5865.77
"": H1.2 H2.2 U2.30 U2.33 U2.35 U2.37 U2.39

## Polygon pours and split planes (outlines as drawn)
GND on Inner2 (solid, remove dead copper, pour order 0): 3600.24,5161.26 5761.49,5161.26 5761.49,7322.51 3600.24,7322.51
GND on Inner1 (split plane): 4418.32,6142.09 4418.32,6215.29 4450.02,6215.29 4450.02,6142.09
GND on Inner1 (split plane): 4450.02,6288.48 4450.02,6215.29 4418.32,6215.29 4418.32,6288.48
GND on Inner1 (split plane): 3701.1,5655.33 3701.1,5699 3734.77,5699 3734.77,5655.33
GND on Inner1 (split plane): 3717.94,5715.83 3761.6,5715.83 3761.6,5682.17 3717.94,5682.17
GND on Inner1 (split plane): 4950.02,6215.29 4950.02,6142.09 4918.32,6142.09 4918.32,6215.29
GND on Inner1 (split plane): 4918.32,6215.29 4918.32,6288.48 4950.02,6288.48 4950.02,6215.29
GND on Inner1 (split plane): 4950.02,6970.41 4950.02,6897.21 4918.32,6897.21 4918.32,6970.41
GND on Inner1 (split plane): 4918.32,6970.41 4918.32,7043.6 4950.02,7043.6 4950.02,6970.41
GND on Inner1 (split plane): 5450.02,6970.41 5450.02,6897.21 5418.32,6897.21 5418.32,6970.41
GND on Inner1 (split plane): 5418.32,6970.41 5418.32,7043.6 5450.02,7043.6 5450.02,6970.41
GND on Inner1 (split plane): 3950.02,6215.29 3950.02,6142.09 3918.32,6142.09 3918.32,6215.29
GND on Inner1 (split plane): 3918.32,6215.29 3918.32,6288.48 3950.02,6288.48 3950.02,6215.29
GND on Inner1 (split plane): 3950.02,6970.41 3950.02,6897.21 3918.32,6897.21 3918.32,6970.41
GND on Inner1 (split plane): 3918.32,6970.41 3918.32,7043.6 3950.02,7043.6 3950.02,6970.41
GND on Inner1 (split plane): 5450.02,6215.29 5450.02,6142.09 5418.32,6142.09 5418.32,6215.29
GND on Inner1 (split plane): 5418.32,6215.29 5418.32,6288.48 5450.02,6288.48 5450.02,6215.29
GND on Inner1 (split plane): 5612.57,5690.73 5612.57,5731.93 5643.77,5731.93 5643.77,5690.73
GND on Inner1 (split plane): 5612.57,5649.53 5612.57,5690.73 5643.77,5690.73 5643.77,5649.53
GND on Inner1 (split plane): 5586.97,5706.33 5628.17,5706.33 5628.17,5675.13 5586.97,5675.13

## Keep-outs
Board Outline Layer:
  lines w10 net "": 3644.98,5341.03 ccw(c3764.98,5341.03) 3764.98,5221.03 5600.54,5221.03 ccw(c5600.54,5341.03) 5720.54,5341.03 5720.54,6988.58 ccw(c5600.54,6988.58) 5600.54,7108.58 3764.98,7108.58 ccw(c3764.98,6988.58) 3644.98,6988.58 3644.98,5341.03

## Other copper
Bottom Layer:
  region net +5V: 5379.37,5381.38 5431.34,5381.38 cw(c5431.34,5351.38) 5461.34,5351.38 5461.34,5270.77 cw(c5431.34,5270.77) 5431.34,5240.77 5379.37,5240.77 cw(c5379.37,5270.77) 5349.37,5270.77 5349.37,5351.38 cw(c5379.37,5351.38)

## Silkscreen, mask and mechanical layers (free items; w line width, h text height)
Top Silkscreen Layer:
  text "JLCJLCJLCJLC" at 5645,6299.24 h51.92 r90
  text "EXT_CHAIN" at 3652.4,5982.42 h29.2
  text "JasonYANG17 V1.2" at 4631.94,5939.93 h51.92
  text "BAV99" at 4012.95,5886.16 h29.2
  text "EXT_CHAIN" at 5308.47,5881 h29.2
  text "NC" at 5508.85,5780.04 h29.2
  text "GND" at 5478.66,5677.08 h29.2
  text "100k" at 3788.23,5602.16 h29.2
  text "GND" at 3673.33,5593.94 h29.2
  text "11" at 4954.26,5422.6 h42.19
  text "9" at 4764.01,5422.45 h42.49
  text "GND" at 5135.52,5422.16 h29.2
  text "10" at 4848.26,5420.6 h42.19
  text "12" at 5050.26,5420.6 h42.19
  text "EXT_T" at 5250.95,5420.16 h29.2
  text "8" at 4662.01,5418.45 h42.49
  text "6" at 4464.01,5416.45 h42.49
  text "7" at 4566.01,5416.45 h42.49
  text "1" at 3968.01,5414.45 h42.49
  text "2" at 4066.01,5414.45 h42.49
  text "4" at 4258.01,5414.45 h42.49
  text "5" at 4362.01,5414.45 h42.49
  text "3" at 4162.01,5412.45 h42.49
Bottom Silkscreen Layer:
  text "14" at 5008.26,5422.6 h42.19
  text "GND" at 5217.52,5422.16 h29.2
  text "16" at 4808.26,5420.6 h42.19
  text "15" at 4908.26,5420.6 h42.19
  text "13" at 5110.26,5420.6 h42.19
  text "3V3" at 5319.52,5420.16 h29.2
  text "5V" at 5406.8,5420.16 h29.2
  text "24" at 4016.26,5418.6 h42.19
  text "18" at 4606.26,5418.6 h42.19
  text "17" at 4708.26,5418.6 h42.19
  text "23" at 4118.26,5416.6 h42.19
  text "22" at 4216.26,5416.6 h42.19
  text "21" at 4314.26,5416.6 h42.19
  text "20" at 4416.26,5416.6 h42.19
  text "19" at 4504.26,5416.6 h42.19
Mechanical Layer:
  circle w1 net "": c3764.19,5340.86 r78.5
  circle w1 net "": c5590.78,5341.59 r78.5
Mech6:
  lines w6 net "": 3000,6245.07 5789.42,6245.07 ; 3659.91,7158.44 3779.91,7158.44 3779.91,7278.44 3659.91,7278.44 3659.91,7158.44 ; 3660.69,5212.02 3780.69,5212.02 3780.69,5332.02 3660.69,5332.02 3660.69,5212.02
  lines w10 net "": 3536.41,6190.76 5406.86,6190.76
